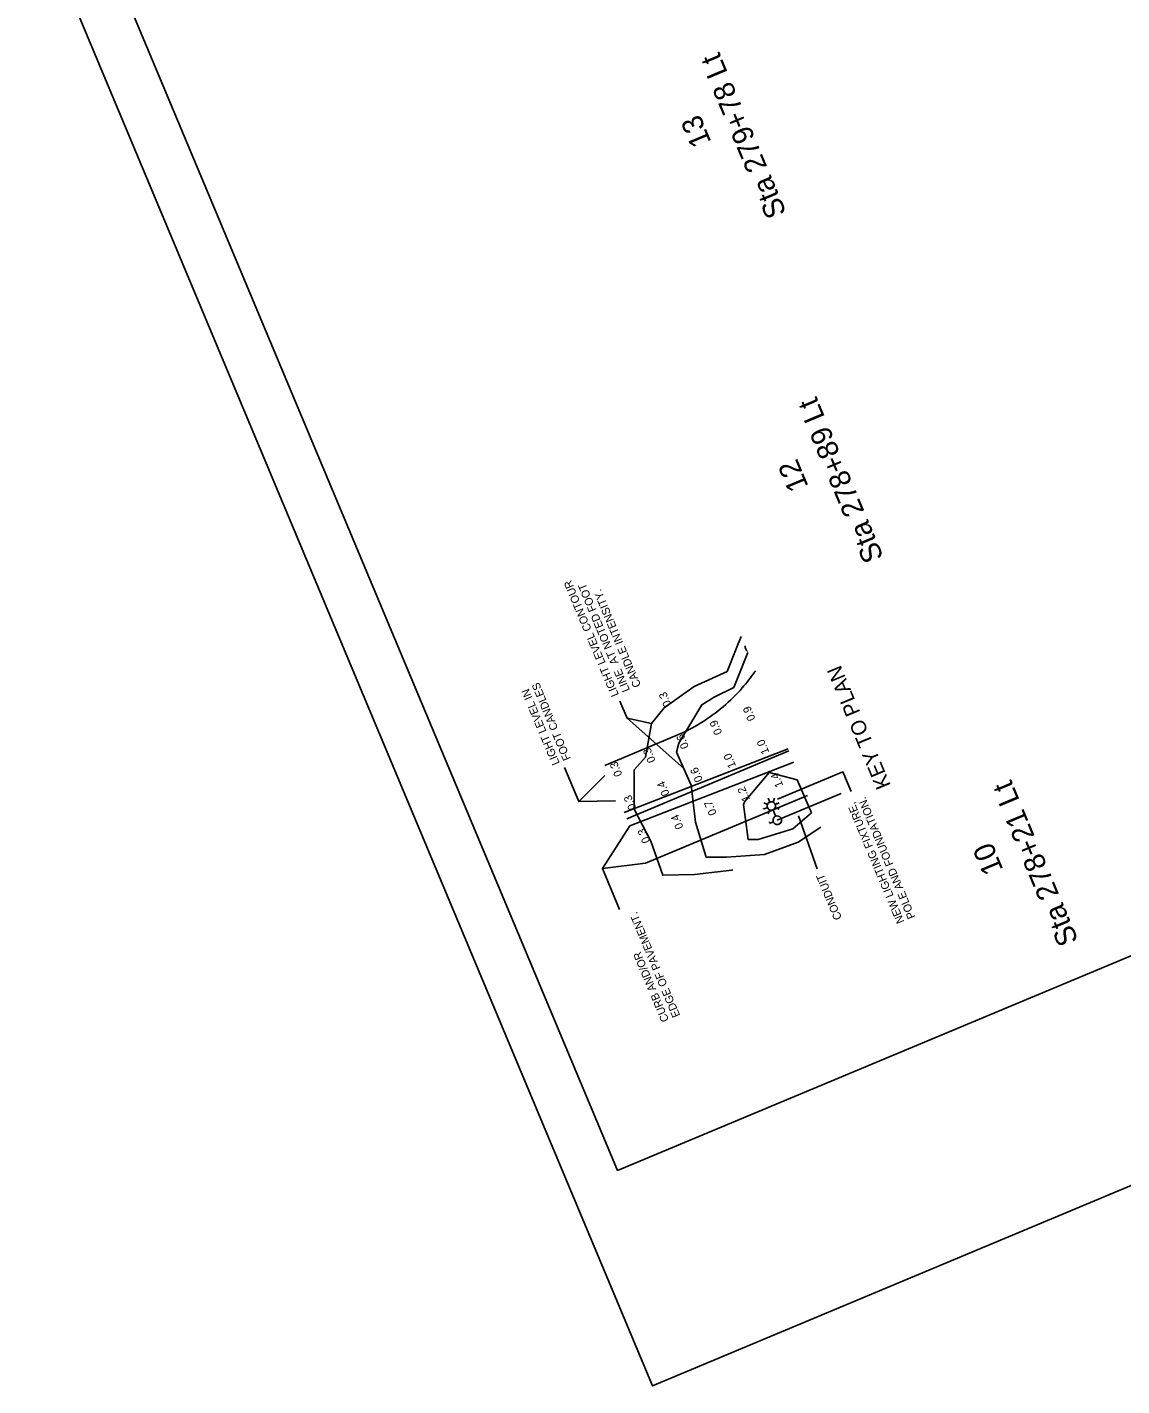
# Model space of a CAD drawing. Extents: x 1111244 to 1112080, y 617020 to 618016.
# Drawn here: x 1111453.4 to 1111662.3, y 617019.6 to 617279 of the extents above; entities that cross this region are included whole.
import ezdxf

# ---------------------------------------------------------------- set-up
doc = ezdxf.new("R2010")
doc.units = 0
for name, color, linetype in [('ANNOTATION', 7, 'Continuous'), ('BORDER', 7, 'Continuous'), ('D_Lighting_Text', 7, 'Continuous'), ('D_Utilities_Pole_StreetLight', 7, 'Continuous'), ('Default', 7, 'Continuous'), ('Liting Text', 7, 'Continuous'), ('PLOT BOUNDARY', 7, 'Continuous')]:
    doc.layers.add(name, color=color, linetype=linetype)

msp = doc.modelspace()

# ---------------------------------------------------------------- linework, layer by layer
at = {"layer": 'ANNOTATION'}
for p, q in [((1111567.83, 617147.03), (1111578.67, 617137.43)), ((1111577.19, 617143.73), (1111563.57, 617138.02)), ((1111598.57, 617141.2), (1111567.31, 617129.06)), ((1111598.74, 617140.8), (1111567.81, 617127.86)), ((1111568.37, 617126.52), (1111599.64, 617138.66)), ((1111558.62, 617131.14), (1111563.59, 617136.11)), ((1111571.35, 617119.39), (1111602.28, 617132.33)), ((1111593.89, 617129.77), (1111593.87, 617129.81)), ((1111596.43, 617130.83), (1111596.41, 617130.87)), ((1111594.95, 617127.23), (1111594.93, 617127.27)), ((1111596.22, 617127.3), (1111596.22, 617127.3)), ((1111596.35, 617126.98), (1111596.35, 617126.98)), ((1111596.54, 617127.43), (1111596.54, 617127.43)), ((1111596.67, 617127.11), (1111596.67, 617127.11)), ((1111604.1, 617118.29), (1111600.54, 617128.42)), ((1111563.14, 617118.39), (1111571.35, 617119.39))]:
    msp.add_line(p, q, dxfattribs=at)
for points in [[(1111588.04, 617118.1), (1111587.84, 617118.05), (1111580.73, 617117.22), (1111574.64, 617117.08), (1111572.38, 617123.6), (1111569.17, 617129.72), (1111569.19, 617137.19), (1111571.37, 617139.63), (1111572.48, 617146.03), (1111574.92, 617149.01), (1111580.67, 617153.08), (1111586.92, 617155.97), (1111588.67, 617160.28), (1111589.63, 617162.62)], [(1111604.82, 617126.23), (1111600.52, 617123.41), (1111594.04, 617121.06), (1111586.81, 617120.53), (1111582.91, 617120.55), (1111580.92, 617127.18), (1111580.07, 617134.28), (1111577.28, 617140.58), (1111577.72, 617142.29), (1111582.12, 617149.61), (1111584.45, 617151.05), (1111588.19, 617152.94), (1111590.9, 617159.59)], [(1111566.48, 617150.28), (1111567.83, 617147.03), (1111572.48, 617146.03)], [(1111555.91, 617137.63), (1111558.62, 617131.14), (1111565.64, 617131.31)], [(1111603.05, 617128.97), (1111600.3, 617135.29), (1111594.97, 617136.69), (1111590.23, 617131.07), (1111590.07, 617130.58), (1111590.94, 617123.91), (1111592.86, 617123.89), (1111599.47, 617125.92), (1111603.05, 617128.97)], [(1111610.58, 617133.04), (1111609.02, 617136.79), (1111596.55, 617131.58)], [(1111566.42, 617110.54), (1111563.14, 617118.39), (1111568.37, 617126.52)]]:
    msp.add_lwpolyline(points, dxfattribs=at)
for centre, major_axis, start_param, end_param in [((1111591.74, 617160.79), (0.3, 1.34), 1.737973, 2.633498), ((1111563.93, 617175.49), (7.48, 33.61), 4.213502, 4.323837), ((1111563.93, 617175.49), (7.48, 33.61), 4.323837, 4.333024), ((1111563.93, 617175.49), (7.48, 33.61), 4.064294, 4.213502), ((1111563.93, 617175.49), (7.48, 33.61), 3.756531, 4.064294)]:
    msp.add_ellipse(centre, major_axis=major_axis, ratio=0.998974, start_param=start_param, end_param=end_param, dxfattribs=at)
at = {"layer": 'BORDER'}
for p, q in [((1111257.07, 617798.63), (1111566.01, 617060.69)), ((1111566.01, 617060.69), (1112050.29, 617263.43))]:
    msp.add_line(p, q, dxfattribs=at)
at = {"layer": 'D_Utilities_Pole_StreetLight'}
for p, q in [((1111595.08, 617131.03), (1111594.77, 617131.77)), ((1111595.69, 617131.03), (1111596, 617131.77)), ((1111594.64, 617129.98), (1111593.9, 617129.68)), ((1111594.64, 617130.6), (1111593.91, 617130.9)), ((1111595.08, 617129.55), (1111594.77, 617128.81)), ((1111596.19, 617128.34), (1111595.69, 617129.55)), ((1111596.12, 617130.59), (1111596.86, 617130.9)), ((1111596.12, 617129.98), (1111596.86, 617129.68)), ((1111595.74, 617127.27), (1111594.99, 617126.95)), ((1111597.26, 617127.89), (1111598.02, 617128.21))]:
    msp.add_line(p, q, dxfattribs=at)
for centre, major_axis in [((1111595.38, 617130.29), (-0.174, -0.782)), ((1111596.5, 617127.58), (0.178, 0.801))]:
    msp.add_ellipse(centre, major_axis=major_axis, ratio=0.998974, dxfattribs=at)
at = {"layer": 'Default'}
msp.add_lwpolyline([(1111572.69, 617019.61), (1111244.44, 617803.67), (1111751.77, 618016.07), (1112080.02, 617232.01)], close=True, dxfattribs=at)
at = {"layer": 'Liting Text'}
msp.add_line((1111596.5, 617127.58), (1111608.73, 617132.7), dxfattribs=at)
at = {"layer": 'PLOT BOUNDARY'}
msp.add_lwpolyline([(1112080.02, 617232.01), (1111751.77, 618016.07), (1111244.44, 617803.67), (1111572.69, 617019.61)], close=True, dxfattribs=at)

# ---------------------------------------------------------------- texts
at = {"layer": 'ANNOTATION'}
for s, height, p in [('LIGHT LEVEL CONTOUR', 1.528, (1111566.31, 617151.53)), ('LINE  AT NOTED FOOT', 1.528, (1111568.42, 617152.42)), ('CANDLE INTENSITY.', 1.528, (1111570.54, 617153.3)), ('KEY TO PLAN', 2.8603, (1111618.21, 617134.22)), ('LIGHT LEVEL IN', 1.528, (1111555.02, 617138.46)), ('FOOT CANDLES', 1.528, (1111557.13, 617139.34)), ('0.3', 1.528, (1111576.33, 617149.6)), ('0.9', 1.528, (1111592.37, 617146.9)), ('0.9', 1.528, (1111586.02, 617144.24)), ('0.6', 1.528, (1111579.67, 617141.58)), ('1.0', 1.528, (1111595.02, 617140.54)), ('0.3', 1.528, (1111573.32, 617138.92)), ('1.0', 1.528, (1111588.67, 617137.89)), ('0.3', 1.528, (1111566.97, 617136.27)), ('0.6', 1.528, (1111582.32, 617135.23)), ('1.4', 1.528, (1111597.67, 617134.19)), ('0.4', 1.528, (1111575.98, 617132.57)), ('1.2', 1.528, (1111591.33, 617131.53)), ('0.3', 1.528, (1111569.63, 617129.91)), ('POLE AND FOUNDATION.', 1.528, (1111622.9, 617109.11)), ('0.7', 1.528, (1111584.98, 617128.87)), ('NEW LIGHTING FIXTURE,', 1.528, (1111620.79, 617108.23)), ('0.4', 1.528, (1111578.63, 617126.22)), ('0.3', 1.528, (1111572.28, 617123.56)), ('CONDUIT', 1.528, (1111608.87, 617108.91)), ('EDGE OF PAVEMENT.', 1.528, (1111578, 617090.31)), ('CURB AND/OR', 1.528, (1111575.88, 617089.43))]:
    msp.add_text(s, height=height, rotation=112.6579, dxfattribs=at).set_placement(p)
at = {"layer": 'D_Lighting_Text'}
for s, p in [('Sta 279+78 Lt', (1111598.31, 617243.49)), ('13', (1111583.97, 617257.03)), ('Sta 278+89 Lt', (1111616.86, 617177.74)), ('12', (1111602.52, 617191.29)), ('Sta 278+21 Lt', (1111654.03, 617104.59)), ('10', (1111639.69, 617118.14))]:
    msp.add_text(s, height=4, rotation=112.7167, dxfattribs=at).set_placement(p)

doc.saveas('drawing.dxf')
